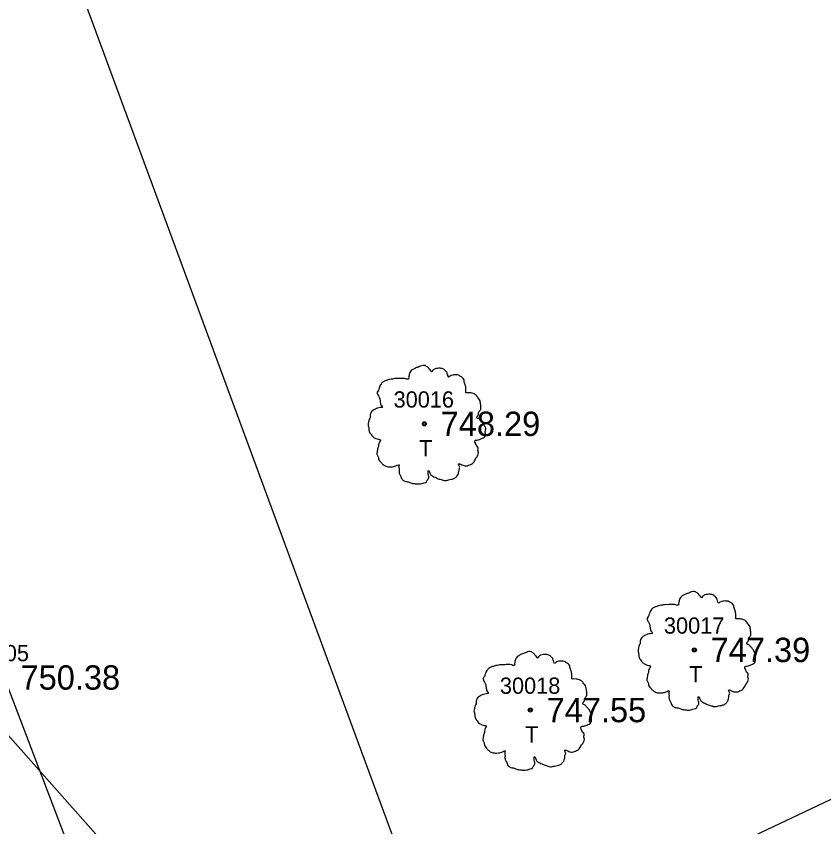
# Model space of a CAD drawing. Extents: x 1375131 to 1378678, y 999028 to 1004053.
# Drawn here: x 1376716.12 to 1376765.86, y 1002931.35 to 1002981.25 of the extents above; entities that cross this region are included whole.
import ezdxf

# ---------------------------------------------------------------- set-up
doc = ezdxf.new("R2010")
doc.units = 0
for name, color, linetype in [('RD_EX_Driveway', 7, 'Continuous'), ('RD_EX_Driveway_txCode', 7, 'Continuous'), ('RD_EX_RW', 7, 'Continuous'), ('RD_EX_SU_Elec', 7, 'Continuous'), ('RD_EX_TX_Driveway_ELEV', 7, 'Continuous'), ('RD_EX_TX_VEG_ELEV', 7, 'Continuous'), ('RD_EX_VEG', 7, 'Continuous'), ('RD_EX_VEG_txCode', 7, 'Continuous'), ('RD_SMD_Locator', 7, 'Continuous')]:
    doc.layers.add(name, color=color, linetype=linetype)

msp = doc.modelspace()

# ---------------------------------------------------------------- linework, layer by layer
at = {"layer": 'RD_EX_Driveway'}
msp.add_lwpolyline([(1376706.507, 1002954.761), (1376715.388, 1002940.545), (1376723.048, 1002920.461), (1376726.876, 1002920.427), (1376736.336, 1002921.326), (1376751.407, 1002925.999), (1376775.28, 1002937.302), (1376791.557, 1002941.719), (1376806.993, 1002947.414)], dxfattribs=at)
at = {"layer": 'RD_EX_RW'}
msp.add_line((1376700.002, 1003037.225), (1376809.218, 1002741.498), dxfattribs=at)
at = {"layer": 'RD_EX_SU_Elec'}
msp.add_line((1376639.019, 1003023.14), (1376751.235, 1002896.935), dxfattribs=at)
at = {"layer": 'RD_EX_VEG'}
for centre, radius in [((1376741.261, 1002956.159), 0.125), ((1376741.255, 1002956.15), 0.00005), ((1376757.886, 1002942.243), 0.125), ((1376757.88, 1002942.234), 0.00005), ((1376747.785, 1002938.542), 0.125), ((1376747.779, 1002938.533), 0.00005)]:
    msp.add_circle(centre, radius, dxfattribs=at)
for points in [[(1376741.327, 1002959.743), (1376741.177, 1002959.755), (1376741.015, 1002959.705), (1376740.89, 1002959.655), (1376740.777, 1002959.618), (1376740.665, 1002959.568), (1376740.515, 1002959.48), (1376740.402, 1002959.38), (1376740.34, 1002959.255), (1376740.315, 1002959.143), (1376740.29, 1002959.005), (1376740.29, 1002958.918), (1376740.227, 1002958.905), (1376740.152, 1002958.918), (1376740.028, 1002958.955), (1376739.903, 1002958.955), (1376739.778, 1002958.955), (1376739.603, 1002958.943), (1376739.428, 1002958.943), (1376739.29, 1002958.918), (1376739.128, 1002958.893), (1376738.941, 1002958.831), (1376738.766, 1002958.768), (1376738.616, 1002958.643), (1376738.491, 1002958.406), (1376738.428, 1002958.231), (1376738.353, 1002958.106), (1376738.428, 1002957.881), (1376738.516, 1002957.706), (1376738.528, 1002957.606), (1376738.566, 1002957.394), (1376738.616, 1002957.281), (1376738.678, 1002957.181), (1376738.641, 1002957.169), (1376738.453, 1002957.144), (1376738.303, 1002957.094), (1376738.091, 1002956.981), (1376737.978, 1002956.869), (1376737.928, 1002956.706), (1376737.916, 1002956.532), (1376737.866, 1002956.432), (1376737.829, 1002956.294), (1376737.816, 1002956.257), (1376737.791, 1002956.094), (1376737.841, 1002955.869), (1376737.854, 1002955.694), (1376737.916, 1002955.582), (1376737.991, 1002955.495), (1376738.078, 1002955.37), (1376738.278, 1002955.257), (1376738.441, 1002955.207), (1376738.541, 1002955.195), (1376738.453, 1002954.945), (1376738.428, 1002954.77), (1376738.366, 1002954.57), (1376738.366, 1002954.532), (1376738.341, 1002954.295), (1376738.416, 1002954.133), (1376738.453, 1002953.945), (1376738.541, 1002953.833), (1376738.678, 1002953.683), (1376738.841, 1002953.57), (1376739.09, 1002953.508), (1376739.29, 1002953.52), (1376739.578, 1002953.608), (1376739.703, 1002953.645), (1376739.69, 1002953.558), (1376739.703, 1002953.37), (1376739.703, 1002953.158), (1376739.778, 1002952.996), (1376739.828, 1002952.858), (1376739.903, 1002952.733), (1376740.065, 1002952.621), (1376740.265, 1002952.583), (1376740.477, 1002952.508), (1376740.702, 1002952.471), (1376740.952, 1002952.458), (1376741.252, 1002952.533), (1376741.389, 1002952.596), (1376741.439, 1002952.683), (1376741.539, 1002952.871), (1376741.514, 1002952.983), (1376741.527, 1002953.283), (1376741.577, 1002953.195), (1376741.664, 1002953.021), (1376741.914, 1002952.871), (1376742.114, 1002952.783), (1376742.352, 1002952.708), (1376742.501, 1002952.671), (1376742.739, 1002952.708), (1376742.926, 1002952.746), (1376743.114, 1002952.808), (1376743.264, 1002952.946), (1376743.351, 1002953.083), (1376743.376, 1002953.22), (1376743.414, 1002953.408), (1376743.439, 1002953.495)], [(1376743.439, 1002953.495), (1376743.401, 1002953.583), (1376743.376, 1002953.708), (1376743.414, 1002953.695), (1376743.501, 1002953.67), (1376743.638, 1002953.608), (1376743.751, 1002953.57), (1376743.913, 1002953.583), (1376744.051, 1002953.633), (1376744.276, 1002953.77), (1376744.413, 1002954.008), (1376744.551, 1002954.208), (1376744.588, 1002954.37), (1376744.563, 1002954.482), (1376744.551, 1002954.732), (1376744.451, 1002954.857), (1376744.426, 1002954.92), (1376744.376, 1002955.12), (1376744.413, 1002955.145), (1376744.551, 1002955.17), (1376744.738, 1002955.232), (1376744.875, 1002955.295), (1376744.988, 1002955.382), (1376745.025, 1002955.495), (1376745.013, 1002955.694), (1376745.038, 1002955.894), (1376745, 1002955.969), (1376744.95, 1002956.044), (1376744.913, 1002956.144), (1376744.838, 1002956.219), (1376744.788, 1002956.294), (1376744.738, 1002956.344), (1376744.676, 1002956.419), (1376744.588, 1002956.482), (1376744.513, 1002956.507), (1376744.488, 1002956.582), (1376744.563, 1002956.681), (1376744.588, 1002956.731), (1376744.601, 1002956.844), (1376744.713, 1002957.019), (1376744.738, 1002957.219), (1376744.713, 1002957.431), (1376744.688, 1002957.569), (1376744.613, 1002957.706), (1376744.513, 1002957.831), (1376744.451, 1002957.918), (1376744.363, 1002957.981), (1376744.201, 1002958.043), (1376744.076, 1002958.068), (1376743.901, 1002958.068), (1376743.801, 1002958.093), (1376743.813, 1002958.118), (1376743.813, 1002958.193), (1376743.813, 1002958.331), (1376743.776, 1002958.556), (1376743.701, 1002958.806), (1376743.701, 1002958.818), (1376743.651, 1002958.943), (1376743.539, 1002959.043), (1376743.451, 1002959.093), (1376743.351, 1002959.155), (1376743.226, 1002959.168), (1376743.076, 1002959.168), (1376742.939, 1002959.143), (1376742.839, 1002959.093), (1376742.751, 1002959.03), (1376742.714, 1002959.105), (1376742.664, 1002959.255), (1376742.639, 1002959.33), (1376742.564, 1002959.418), (1376742.452, 1002959.518), (1376742.227, 1002959.58), (1376741.914, 1002959.543), (1376741.764, 1002959.443), (1376741.689, 1002959.355), (1376741.664, 1002959.418), (1376741.564, 1002959.518), (1376741.514, 1002959.605), (1376741.427, 1002959.668), (1376741.352, 1002959.718), (1376741.302, 1002959.743)], [(1376757.952, 1002945.827), (1376757.802, 1002945.839), (1376757.64, 1002945.789), (1376757.515, 1002945.739), (1376757.402, 1002945.702), (1376757.29, 1002945.652), (1376757.14, 1002945.564), (1376757.027, 1002945.464), (1376756.965, 1002945.339), (1376756.94, 1002945.227), (1376756.915, 1002945.089), (1376756.915, 1002945.002), (1376756.852, 1002944.989), (1376756.777, 1002945.002), (1376756.653, 1002945.039), (1376756.528, 1002945.039), (1376756.403, 1002945.039), (1376756.228, 1002945.027), (1376756.053, 1002945.027), (1376755.915, 1002945.002), (1376755.753, 1002944.977), (1376755.566, 1002944.915), (1376755.391, 1002944.852), (1376755.241, 1002944.727), (1376755.116, 1002944.49), (1376755.053, 1002944.315), (1376754.978, 1002944.19), (1376755.053, 1002943.965), (1376755.141, 1002943.79), (1376755.153, 1002943.69), (1376755.191, 1002943.478), (1376755.241, 1002943.365), (1376755.303, 1002943.265), (1376755.266, 1002943.253), (1376755.078, 1002943.228), (1376754.928, 1002943.178), (1376754.716, 1002943.065), (1376754.603, 1002942.953), (1376754.553, 1002942.79), (1376754.541, 1002942.616), (1376754.491, 1002942.516), (1376754.454, 1002942.378), (1376754.441, 1002942.341), (1376754.416, 1002942.178), (1376754.466, 1002941.953), (1376754.479, 1002941.778), (1376754.541, 1002941.666), (1376754.616, 1002941.579), (1376754.703, 1002941.454), (1376754.903, 1002941.341), (1376755.066, 1002941.291), (1376755.166, 1002941.279), (1376755.078, 1002941.029), (1376755.053, 1002940.854), (1376754.991, 1002940.654), (1376754.991, 1002940.616), (1376754.966, 1002940.379), (1376755.041, 1002940.217), (1376755.078, 1002940.029), (1376755.166, 1002939.917), (1376755.303, 1002939.767), (1376755.466, 1002939.654), (1376755.715, 1002939.592), (1376755.915, 1002939.604), (1376756.203, 1002939.692), (1376756.328, 1002939.729), (1376756.315, 1002939.642), (1376756.328, 1002939.454), (1376756.328, 1002939.242), (1376756.403, 1002939.08), (1376756.453, 1002938.942), (1376756.528, 1002938.817), (1376756.69, 1002938.705), (1376756.89, 1002938.667), (1376757.102, 1002938.592), (1376757.327, 1002938.555), (1376757.577, 1002938.542), (1376757.877, 1002938.617), (1376758.014, 1002938.68), (1376758.064, 1002938.767), (1376758.164, 1002938.955), (1376758.139, 1002939.067), (1376758.152, 1002939.367), (1376758.202, 1002939.279), (1376758.289, 1002939.105), (1376758.539, 1002938.955), (1376758.739, 1002938.867), (1376758.977, 1002938.792), (1376759.126, 1002938.755), (1376759.364, 1002938.792), (1376759.551, 1002938.83), (1376759.739, 1002938.892), (1376759.889, 1002939.03), (1376759.976, 1002939.167), (1376760.001, 1002939.304), (1376760.039, 1002939.492), (1376760.064, 1002939.579)], [(1376760.064, 1002939.579), (1376760.026, 1002939.667), (1376760.001, 1002939.792), (1376760.039, 1002939.779), (1376760.126, 1002939.754), (1376760.263, 1002939.692), (1376760.376, 1002939.654), (1376760.538, 1002939.667), (1376760.676, 1002939.717), (1376760.901, 1002939.854), (1376761.038, 1002940.092), (1376761.176, 1002940.292), (1376761.213, 1002940.454), (1376761.188, 1002940.566), (1376761.176, 1002940.816), (1376761.076, 1002940.941), (1376761.051, 1002941.004), (1376761.001, 1002941.204), (1376761.038, 1002941.229), (1376761.176, 1002941.254), (1376761.363, 1002941.316), (1376761.5, 1002941.379), (1376761.613, 1002941.466), (1376761.65, 1002941.579), (1376761.638, 1002941.778), (1376761.663, 1002941.978), (1376761.625, 1002942.053), (1376761.575, 1002942.128), (1376761.538, 1002942.228), (1376761.463, 1002942.303), (1376761.413, 1002942.378), (1376761.363, 1002942.428), (1376761.301, 1002942.503), (1376761.213, 1002942.566), (1376761.138, 1002942.591), (1376761.113, 1002942.666), (1376761.188, 1002942.765), (1376761.213, 1002942.815), (1376761.226, 1002942.928), (1376761.338, 1002943.103), (1376761.363, 1002943.303), (1376761.338, 1002943.515), (1376761.313, 1002943.653), (1376761.238, 1002943.79), (1376761.138, 1002943.915), (1376761.076, 1002944.002), (1376760.988, 1002944.065), (1376760.826, 1002944.127), (1376760.701, 1002944.152), (1376760.526, 1002944.152), (1376760.426, 1002944.177), (1376760.438, 1002944.202), (1376760.438, 1002944.277), (1376760.438, 1002944.415), (1376760.401, 1002944.64), (1376760.326, 1002944.89), (1376760.326, 1002944.902), (1376760.276, 1002945.027), (1376760.164, 1002945.127), (1376760.076, 1002945.177), (1376759.976, 1002945.239), (1376759.851, 1002945.252), (1376759.701, 1002945.252), (1376759.564, 1002945.227), (1376759.464, 1002945.177), (1376759.376, 1002945.114), (1376759.339, 1002945.189), (1376759.289, 1002945.339), (1376759.264, 1002945.414), (1376759.189, 1002945.502), (1376759.077, 1002945.602), (1376758.852, 1002945.664), (1376758.539, 1002945.627), (1376758.389, 1002945.527), (1376758.314, 1002945.439), (1376758.289, 1002945.502), (1376758.189, 1002945.602), (1376758.139, 1002945.689), (1376758.052, 1002945.752), (1376757.977, 1002945.802), (1376757.927, 1002945.827)], [(1376747.851, 1002942.126), (1376747.701, 1002942.138), (1376747.539, 1002942.088), (1376747.414, 1002942.038), (1376747.301, 1002942.001), (1376747.189, 1002941.951), (1376747.039, 1002941.863), (1376746.926, 1002941.763), (1376746.864, 1002941.638), (1376746.839, 1002941.526), (1376746.814, 1002941.388), (1376746.814, 1002941.301), (1376746.751, 1002941.288), (1376746.676, 1002941.301), (1376746.552, 1002941.338), (1376746.427, 1002941.338), (1376746.302, 1002941.338), (1376746.127, 1002941.326), (1376745.952, 1002941.326), (1376745.814, 1002941.301), (1376745.652, 1002941.276), (1376745.464, 1002941.214), (1376745.29, 1002941.151), (1376745.14, 1002941.026), (1376745.015, 1002940.789), (1376744.952, 1002940.614), (1376744.877, 1002940.489), (1376744.952, 1002940.264), (1376745.04, 1002940.089), (1376745.052, 1002939.989), (1376745.09, 1002939.777), (1376745.14, 1002939.664), (1376745.202, 1002939.564), (1376745.165, 1002939.552), (1376744.977, 1002939.527), (1376744.827, 1002939.477), (1376744.615, 1002939.364), (1376744.502, 1002939.252), (1376744.452, 1002939.089), (1376744.44, 1002938.915), (1376744.39, 1002938.815), (1376744.352, 1002938.677), (1376744.34, 1002938.64), (1376744.315, 1002938.477), (1376744.365, 1002938.252), (1376744.377, 1002938.077), (1376744.44, 1002937.965), (1376744.515, 1002937.878), (1376744.602, 1002937.753), (1376744.802, 1002937.64), (1376744.965, 1002937.59), (1376745.065, 1002937.578), (1376744.977, 1002937.328), (1376744.952, 1002937.153), (1376744.89, 1002936.953), (1376744.89, 1002936.915), (1376744.865, 1002936.678), (1376744.94, 1002936.516), (1376744.977, 1002936.328), (1376745.065, 1002936.216), (1376745.202, 1002936.066), (1376745.365, 1002935.953), (1376745.614, 1002935.891), (1376745.814, 1002935.903), (1376746.102, 1002935.991), (1376746.227, 1002936.028), (1376746.214, 1002935.941), (1376746.227, 1002935.753), (1376746.227, 1002935.541), (1376746.302, 1002935.379), (1376746.352, 1002935.241), (1376746.427, 1002935.116), (1376746.589, 1002935.004), (1376746.789, 1002934.966), (1376747.001, 1002934.891), (1376747.226, 1002934.854), (1376747.476, 1002934.841), (1376747.776, 1002934.916), (1376747.913, 1002934.979), (1376747.963, 1002935.066), (1376748.063, 1002935.254), (1376748.038, 1002935.366), (1376748.051, 1002935.666), (1376748.101, 1002935.578), (1376748.188, 1002935.404), (1376748.438, 1002935.254), (1376748.638, 1002935.166), (1376748.875, 1002935.091), (1376749.025, 1002935.054), (1376749.263, 1002935.091), (1376749.45, 1002935.129), (1376749.638, 1002935.191), (1376749.788, 1002935.329), (1376749.875, 1002935.466), (1376749.9, 1002935.603), (1376749.938, 1002935.791), (1376749.963, 1002935.878)], [(1376749.963, 1002935.878), (1376749.925, 1002935.966), (1376749.9, 1002936.091), (1376749.938, 1002936.078), (1376750.025, 1002936.053), (1376750.162, 1002935.991), (1376750.275, 1002935.953), (1376750.437, 1002935.966), (1376750.575, 1002936.016), (1376750.8, 1002936.153), (1376750.937, 1002936.391), (1376751.075, 1002936.591), (1376751.112, 1002936.753), (1376751.087, 1002936.865), (1376751.075, 1002937.115), (1376750.975, 1002937.24), (1376750.95, 1002937.303), (1376750.9, 1002937.503), (1376750.937, 1002937.528), (1376751.075, 1002937.553), (1376751.262, 1002937.615), (1376751.399, 1002937.678), (1376751.512, 1002937.765), (1376751.549, 1002937.878), (1376751.537, 1002938.077), (1376751.562, 1002938.277), (1376751.524, 1002938.352), (1376751.474, 1002938.427), (1376751.437, 1002938.527), (1376751.362, 1002938.602), (1376751.312, 1002938.677), (1376751.262, 1002938.727), (1376751.199, 1002938.802), (1376751.112, 1002938.865), (1376751.037, 1002938.89), (1376751.012, 1002938.965), (1376751.087, 1002939.064), (1376751.112, 1002939.114), (1376751.124, 1002939.227), (1376751.237, 1002939.402), (1376751.262, 1002939.602), (1376751.237, 1002939.814), (1376751.212, 1002939.952), (1376751.137, 1002940.089), (1376751.037, 1002940.214), (1376750.975, 1002940.301), (1376750.887, 1002940.364), (1376750.725, 1002940.426), (1376750.6, 1002940.451), (1376750.425, 1002940.451), (1376750.325, 1002940.476), (1376750.337, 1002940.501), (1376750.337, 1002940.576), (1376750.337, 1002940.714), (1376750.3, 1002940.939), (1376750.225, 1002941.189), (1376750.225, 1002941.201), (1376750.175, 1002941.326), (1376750.062, 1002941.426), (1376749.975, 1002941.476), (1376749.875, 1002941.538), (1376749.75, 1002941.551), (1376749.6, 1002941.551), (1376749.463, 1002941.526), (1376749.363, 1002941.476), (1376749.275, 1002941.413), (1376749.238, 1002941.488), (1376749.188, 1002941.638), (1376749.163, 1002941.713), (1376749.088, 1002941.801), (1376748.975, 1002941.901), (1376748.751, 1002941.963), (1376748.438, 1002941.926), (1376748.288, 1002941.826), (1376748.213, 1002941.738), (1376748.188, 1002941.801), (1376748.088, 1002941.901), (1376748.038, 1002941.988), (1376747.951, 1002942.051), (1376747.876, 1002942.101), (1376747.826, 1002942.126)]]:
    msp.add_spline(points, degree=3, dxfattribs=at)
at = {"layer": 'RD_SMD_Locator'}
for centre in [(1376741.261, 1002956.159), (1376757.886, 1002942.243), (1376747.785, 1002938.542)]:
    msp.add_circle(centre, 0.075, dxfattribs=at)

# ---------------------------------------------------------------- texts
at = {"layer": 'RD_EX_Driveway_txCode'}
msp.add_text('30005', height=1, dxfattribs=at).set_placement((1376713.191, 1002941.545))
at = {"layer": 'RD_EX_TX_Driveway_ELEV'}
msp.add_text('750.38', height=1.5, dxfattribs=at).set_placement((1376716.388, 1002939.795))
at = {"layer": 'RD_EX_TX_VEG_ELEV'}
for s, p in [('748.29', (1376742.261, 1002955.409)), ('747.39', (1376758.886, 1002941.493)), ('747.55', (1376748.785, 1002937.792))]:
    msp.add_text(s, height=1.5, dxfattribs=at).set_placement(p)
at = {"layer": 'RD_EX_VEG_txCode'}
for s, p in [('30016', (1376739.363, 1002957.159)), ('T', (1376740.938, 1002954.159)), ('30017', (1376756.012, 1002943.243)), ('T', (1376757.563, 1002940.243)), ('30018', (1376745.911, 1002939.542)), ('T', (1376747.462, 1002936.542))]:
    msp.add_text(s, height=1, dxfattribs=at).set_placement(p)

doc.saveas('drawing.dxf')
